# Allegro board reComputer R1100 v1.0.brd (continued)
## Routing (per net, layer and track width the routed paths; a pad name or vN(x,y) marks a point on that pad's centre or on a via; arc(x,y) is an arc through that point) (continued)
ISO_5V: length 16.1
  BOTTOM w1.016: R117.1 72.55,14.4 71.58,13.42 62.41,13.42 60.07,15.76 U22.4
LORA_3V3: length 7.8
  TOP w0.305: v1(71.25,36.59) 71.09,36.42 C112.2
  BOTTOM w0.305: J14.2 71.25,35.32 v1(71.25,36.59) ; J14.24 v1(59.24,34.03) ; J14.52 v1(44.25,35.32) 44.22,35.34 C114.2
  vias: v1(41.76,26.68) v1(41.76,26.2) v1(42.19,26.71) v1(42.19,26.22) v1(50.75,24.12) v1(50.75,23.66) v1(51.21,24.12) v1(51.21,23.66) v1(59.36,33.59)
LORAWAN_SX1262_CS: length 73.7
  TOP w0.121: v1(27.55,66.39) 28.18,67.02 U12.1
  LYR3 w0.121: v1(54.84,67.02) 55.36,67.02 55.9,66.48 55.9,52.82 56.61,52.11 56.61,37.69 57.03,37.27 57.46,37.27 58.73,36 58.73,33.9 57.69,32.85 57.69,29.27 v1(57.84,29.12)
  LYR6 w0.121: v1(27.55,66.39) 37.3,66.39 37.54,66.64 53.09,66.64 53.83,67.37 54.49,67.37 v1(54.84,67.02)
  BOTTOM w0.121: J14.25 58.84,28.22 58.64,28.42 58.1,28.42 57.84,28.69 v1(57.84,29.12)
LORAWAN_SX1262_RST: length 77.4
  TOP w0.121: U12.2 28.68,66.97 27.92,66.2 27.92,63.82 27.61,63.51 v1(27.61,62.9)
  LYR3 w0.121: v1(68.2,59.91) 69.78,58.33 69.78,47.99 70.89,46.87 70.89,39.35 v1(68.04,36.49)
  LYR6 w0.121: v1(68.2,59.91) 67.27,59.91 62.83,64.34 56.25,64.34 53.23,61.33 29.52,61.33 28.5,62.34 28.17,62.34 v1(27.61,62.9)
  BOTTOM w0.121: J14.10 v1(68.04,36.49)
LORAWAN_SX1302_RST: length 79.1
  TOP w0.121: v1(60.61,34) 60.61,33.67 59.99,33.05 R110.2 ; U12.3 29.18,66.92 28.22,65.97 v1(28.22,63.44)
  LYR3 w0.121: v1(65.48,63.41) 65.48,59.04 66.55,57.97 66.55,41.87 65.89,41.21 65.89,39.66 60.61,34.38 v1(60.61,34)
  LYR6 w0.121: v1(28.22,63.44) 28.78,63.44 29.84,62.38 31.49,62.38 31.85,62.01 52.86,62.01 56.09,65.24 63.65,65.24 v1(65.48,63.41)
LTE_LED_WWAN#: length 142.4
  TOP w0.121: J25.6 15.65,4.12 v1(14.68,5.09)
  LYR3 w0.121: v1(73.97,48.02) 78.08,43.9 78.08,33.36 78.33,33.12 82.41,33.12 84.15,34.85 v1(84.15,36.61) ; v1(24.79,55.49) 24.79,51.31 13.26,39.77 13.26,38.85 12.4,37.99 10.12,37.99 9.45,37.32 9.45,28.89 12.47,25.87 12.47,23.86 10.87,22.26 10.87,13.07 14.84,9.11 14.84,5.24 v1(14.68,5.09)
  LYR6 w0.121: v1(73.97,48.02) 73.74,47.79 52.48,47.79 47.25,53.02 35.71,53.02 35.26,53.48 32.72,53.48 32.26,53.02 29.26,53.02 26.8,55.49 v1(24.79,55.49)
  BOTTOM w0.121: J15.42 v1(84.15,36.61)
LTE_RESET: length 95.2
  TOP w0.121: v1(28.32,62.78) 28.68,63.13 28.68,65.96 29.68,66.96 U12.4
  LYR3 w0.121: v1(94.39,39.91) 94.57,40.09 94.57,42.07 89.82,46.82 v1(89.82,60.59)
  LYR6 w0.121: v1(28.32,62.78) 28.63,62.78 29.47,61.94 31.27,61.94 31.54,61.66 53.09,61.66 56.11,64.68 62.97,64.68 67.21,60.44 69.98,60.44 70.56,59.85 74.2,59.85 74.93,60.59 89.81,60.59 v1(89.82,60.59)
  BOTTOM w0.121: R109.2 v1(94.39,39.91)
NEXTRST: length 44.2
  TOP w0.121: v1(60.86,36.66) 59.79,35.6 58.47,35.6 58.24,35.37 R46.1 ; J4.100 v1(54.2,72.08)
  LYR3 w0.121: v1(54.2,72.08) 54.2,70.73 57.38,67.55 59.13,67.55 61.78,64.91 61.78,44.16 60.86,43.24 v1(60.86,36.66)
NLNKA_LED: length 24.8
  TOP w0.121: R83.1 v1(44.1,23.51) ; U4.21 52.34,37.41 50.9,38.85 46.08,38.85 45.37,38.14 45.37,36.87 v1(45.65,36.59)
  LYR3 w0.121: v1(45.65,36.59) 45.65,36.31 46.08,35.88 46.08,27.34 44.1,25.36 v1(44.1,23.51)
NPIBOOT: length 94.9
  TOP w0.121: v1(38.81,71.11) 40.05,69.87 45.51,69.87 50.01,74.38 54.99,74.38 55.4,74.79 J4.93
  LYR3 w0.121: J6.2 3.02,33.97 6.07,33.97 6.71,34.61 6.71,41.49 8.11,42.89 13.52,42.89 21.49,50.86 21.49,74.76 v1(22.58,75.86)
  LYR6 w0.121: v1(38.81,71.11) 34.52,75.4 23.04,75.4 v1(22.58,75.86)
NPWR_LED: length 122
  TOP w0.121: v1(12.42,5.57) 11.41,5.57 10.65,4.82 J25.1 ; J4.95 55,74.83 54.83,74.65 49.94,74.65 45.4,70.12 40.59,70.12 v1(39.45,71.26)
  LYR3 w0.121: v1(12.42,5.57) 12.42,10.47 7.99,14.9 7.99,21.4 6.36,23.03 6.36,26.5 7.71,27.85 7.71,37.66 9.04,38.99 11.93,38.99 12.25,39.31 12.25,40.19 23.27,51.22 23.27,59.3 23.75,59.78 23.75,63.36 23.24,63.87 23.24,68.92 22.91,69.25 22.91,75.25 v1(23.5,75.83)
  LYR6 w0.121: v1(23.5,75.83) 34.72,75.83 39.3,71.26 v1(39.45,71.26)
NSPD_LED: length 22.8
  TOP w0.121: v1(46.23,36.49) 46.23,38.19 46.61,38.57 50.78,38.57 51.84,37.51 U4.22 ; R84.1 v1(45.14,23.5)
  LYR3 w0.121: v1(46.23,36.49) 46.33,36.39 46.33,27.23 45.08,25.99 45.08,23.56 v1(45.14,23.5)
PCIE_CLK_N: length 88.7
  TOP w0.095: J5.112 71.8,39.03 71.86,39.09 71.86,39.44 72.12,39.7 75.34,39.7 76.58,40.95 76.58,56.3 77.02,56.73 77.64,56.73 77.75,56.84 v1(77.97,56.84)
  LYR6 w0.102: v1(18.93,56.94) 19.03,56.84 29.32,56.84 31.07,58.58 53.22,58.58 55.06,56.74 77.65,56.74 77.75,56.84 v1(77.97,56.84)
  BOTTOM w0.095: v1(18.93,56.94) 18.81,56.83 14.71,56.83 14.6,56.94 J62.53
PCIE_CLK_NREQ: length 90.1
  TOP w0.121: J5.102 75.83,38.75 77.83,40.75 77.83,54.6 78.97,55.74 78.97,62.7 v1(77.19,64.48)
  BOTTOM w0.121: v1(77.19,64.48) 76.17,65.5 56.92,65.5 54.43,63.01 41.38,63.01 36.68,58.31 32.57,58.31 32.04,57.78 22.62,57.78 22.02,57.19 J62.52
PCIE_CLK_P: length 88.6
  TOP w0.095: J5.110 72.2,39.03 72.14,39.09 72.14,39.33 72.24,39.42 73.97,39.42 74.09,39.29 74.45,39.29 74.58,39.42 75.45,39.42 76.86,40.83 76.86,41.19 76.99,41.31 76.99,41.67 76.86,41.79 76.86,54 76.99,54.13 76.99,54.48 76.86,54.61 76.86,54.96 76.99,55.09 76.99,55.45 76.86,55.57 76.86,56.18 77.13,56.45 77.64,56.45 77.75,56.34 v1(77.97,56.34)
  LYR6 w0.102: v1(18.93,56.43) 19.03,56.54 29.45,56.54 31.19,58.28 53.09,58.28 54.93,56.44 77.65,56.44 77.75,56.34 v1(77.97,56.34)
  BOTTOM w0.095: J62.55 14.6,56.44 14.71,56.55 18.81,56.55 v1(18.93,56.43)
PCIE_NRST: length 77
  TOP w0.121: J5.109 72.2,58.32 69.8,60.72 69.8,65.11 69.01,65.9 v1(67.59,65.9)
  BOTTOM w0.121: v1(67.59,65.9) 56.9,65.9 54.26,63.26 41.28,63.26 36.58,58.56 32.46,58.56 31.93,58.03 22.26,58.03 21.91,57.69 J62.50
PCIE_RX_N: length 91.4
  TOP w0.095: J5.118 70.6,39.03 70.66,39.09 70.66,39.64 71.44,40.41 74.42,40.41 75.54,41.53 75.54,58.87 75.86,59.19 76.23,59.19 76.34,59.31 v1(76.56,59.31)
  LYR6 w0.102: v1(18.9,59.94) 19,59.84 28.97,59.84 29.64,60.51 54.05,60.51 57.36,63.82 62.38,63.82 67,59.21 76.24,59.21 76.34,59.31 v1(76.56,59.31)
  BOTTOM w0.095: v1(18.9,59.94) 18.79,59.83 14.71,59.83 14.6,59.94 J62.41
PCIE_RX_P: length 91.4
  TOP w0.095: v1(76.56,58.8) 76.34,58.8 76.23,58.91 75.98,58.91 75.82,58.76 75.82,58.4 75.95,58.28 75.95,57.92 75.82,57.79 75.82,57.44 75.95,57.31 75.95,56.96 75.82,56.83 75.82,44.23 75.95,44.11 75.95,43.75 75.82,43.62 75.82,41.41 75.22,40.82 75.22,40.64 74.97,40.38 74.79,40.38 74.54,40.13 71.55,40.13 70.94,39.52 70.94,39.09 71,39.03 J5.116
  LYR6 w0.102: v1(76.56,58.8) 76.34,58.8 76.24,58.9 66.87,58.9 62.26,63.51 57.48,63.51 54.18,60.21 29.77,60.21 29.1,59.54 19,59.54 v1(18.9,59.43)
  BOTTOM w0.095: J62.43 14.6,59.44 14.71,59.55 18.79,59.55 v1(18.9,59.43)
PCIE_TX_N: length 87.4
  TOP w0.095: v1(74.56,58.43) 74.68,58.32 74.68,44.46 74.55,44.33 74.55,43.98 74.68,43.85 74.68,43.5 74.55,43.37 74.55,43.01 74.68,42.89 74.68,41.89 73.94,41.15 70.4,41.15 69.46,40.21 69.46,39.09 69.4,39.03 J5.124
  LYR6 w0.102: v1(18.9,58.44) 19,58.34 29.04,58.34 30.36,59.65 53.95,59.65 55.86,57.75 70.56,57.75 70.69,57.87 71.05,57.87 71.17,57.75 71.53,57.75 71.66,57.87 72.01,57.87 72.14,57.75 72.49,57.75 72.62,57.87 72.98,57.87 73.1,57.75 73.46,57.75 73.59,57.87 73.94,57.87 74.07,57.75 74.54,57.75 74.67,57.87 74.67,58.33 v1(74.56,58.43)
  BOTTOM w0.095: J62.47 14.6,58.44 14.72,58.33 18.79,58.33 v1(18.9,58.44)
PCIE_TX_P: length 87.4
  TOP w0.095: v1(75.07,58.43) 74.96,58.32 74.96,41.77 74.06,40.87 70.51,40.87 70.3,40.65 70.3,40.49 70.06,40.25 69.89,40.25 69.74,40.1 69.74,39.09 69.8,39.03 J5.122
  LYR6 w0.102: v1(18.9,57.93) 19,58.03 29.17,58.03 30.48,59.35 53.83,59.35 55.73,57.44 74.67,57.44 74.97,57.74 74.97,58.33 v1(75.07,58.43)
  BOTTOM w0.095: v1(18.9,57.93) 18.79,58.05 14.72,58.05 14.6,57.94 J62.49
PCIE_USIM_PRESE: length 34.2
  LYR3 w0.121: v1(84.43,57.82) 85.24,57.01 v1(85.24,37.12)
  BOTTOM w0.121: J15.44 83.35,36.9 83.57,37.12 v1(85.24,37.12) ; R114.2 77.55,54.67 J16.SW 79.86,55.21 82.48,57.82 v1(84.43,57.82)
PL_NLED: length 126.8
  TOP w0.121: v1(69.98,74.94) 69.8,75.12 J4.21 ; v1(11.56,4.76) 11.65,4.67 J25.2
  LYR3 w0.121: v1(11.56,4.76) 11.56,10.63 7.5,14.7 7.5,21.2 5.86,22.83 5.86,26.71 7.21,28.05 7.21,41.28 8.31,42.39 13.72,42.39 22.71,51.37 22.71,60.06 22.84,60.18 22.84,64.45 v1(22.71,64.58)
  BOTTOM w0.121: v1(22.71,64.58) 22.72,64.57 38.3,64.57 39.39,65.66 44.83,65.66 48.34,69.18 61.07,69.18 61.96,70.07 66.86,70.07 67.06,70.27 67.06,71.94 69.98,74.87 v1(69.98,74.94)
POE_12V:
  vias: v1(35.49,44.21) v1(35.49,43.78) v1(35.47,43.33) v1(35.47,42.85) v1(35.94,44.18) v1(35.94,43.75) v1(35.93,43.31) v1(35.93,42.82)
POE_IN_N:
  vias: v1(13.97,8.47) v1(14.18,9) v1(14.46,8.47) v1(19.97,17.66) v1(20.4,17.66) v1(20.83,17.66) v1(25.35,19.67) v1(25.35,19.21) v1(25.78,19.65) v1(25.78,19.19) v1(33.56,16.39) v1(33.56,15.89) v1(33.56,15.43) v1(33.56,14.97)
RS485_POWER_EN: length 96.6
  TOP w0.121: U12.14 v1(30.18,73.27)
  LYR3 w0.121: v1(80.85,24.22) 79.1,24.22 77.75,25.56 77.75,43.6 72.21,49.14 72.21,65.82 v1(70.89,67.14) ; v1(30.76,66.89) 30.76,67.83 29.92,68.67 29.92,73.14 30.04,73.27 v1(30.18,73.27)
  LYR6 w0.121: v1(70.89,67.14) 56.42,67.14 55.83,67.73 53.19,67.73 52.5,67.04 37.47,67.04 37.09,66.66 31.93,66.66 31.7,66.89 v1(30.76,66.89)
RTC_INT: length 6.5
  TOP w0.121: U16.3 v1(11.53,69.76)
  BOTTOM w0.121: C109.1 12.21,73.76 R104.2 10.72,73.22 10.72,70.57 v1(11.53,69.76)
RUN_PG: length 98.2
  TOP w0.121: J4.92 55.8,72.17 55.3,71.67 49.15,71.67 v1(48.9,71.92)
  LYR3 w0.121: v1(48.9,71.92) 48.9,71.72 43.61,66.43 43.61,53.28 34.67,44.33 34.67,31.41 39.21,26.87 39.21,24.99 39.7,24.5 39.7,22.59 38.36,21.25 v1(37.82,21.25)
  LYR6 w0.121: v1(37.82,21.25) 35.84,21.25 34.75,20.15 31.42,20.15 29.75,18.48 18.77,18.48 17.1,16.81 10.97,16.81 v1(9.83,17.94)
  BOTTOM w0.121: R36.2 9.83,17.94 v1(9.83,17.94)
SD_DET: length 19.5
  TOP w0.121: R87.1 18.52,65.9 19.05,65.37 20.53,65.37 21.67,66.51 21.67,72.22 23.83,74.38 27.66,74.38 v1(28.7,73.34) 29.18,72.87 U12.16
SD_VDD_OVERRIDE: length 2.8
  TOP w0.121: J4.73 59.4,78.02 R26.1
TPM_RST: length 70.6
  TOP w0.121: U12.5 30.18,65.62 30.69,65.11 30.69,62.52 30.43,62.27 26.41,62.27 v1(26.08,61.94)
  LYR3 w0.121: v1(17.1,17.56) 17.1,17.59 15.01,19.67 13.06,19.67 12.58,20.15 12.58,23.26 12.97,23.66 12.97,26.07 10,29.04 10,37.09 10.41,37.5 12.67,37.5 23.98,48.81 25.3,48.81 25.96,49.47 25.96,56.05 26.7,56.79 26.7,58.08 26.08,58.69 v1(26.08,61.94)
  BOTTOM w0.121: J13.3 v1(17.1,17.56)
TRCT: length 32.5
  TOP w0.305: v1(47.52,22.1) C88.1 47.09,22.11 R82.2
  BOTTOM w0.305: 50.45,5.79 J10.12 ; 50.45,5.79 50.08,5.79 ; 50.45,5.79 50.27,5.98 ; 50.08,5.79 48.56,4.27 J10.9 ; 50.08,5.79 50.27,5.98 ; 50.27,5.98 J10.5 49,16.79 J10.4 49,20.21 47.52,21.68 v1(47.52,22.1)
UART_3V3: length 103.2
  TOP w0.254: U15.1 35.09,55.19 34.8,55.49 34.8,56.48 v1(34.72,56.55) 34.8,56.63 C100.2 ; R91.1 35.97,50.58 35.59,50.2 30.53,50.2 30.2,50.53 30.2,52.46 30.76,53.02 v1(33.38,53.02) 33.64,53.28 R98.1
  LYR3 w0.381: v1(54.82,21.35) 54.82,20.28 57.61,17.49 57.61,15.25 59.34,13.52 59.34,7.5 v1(59.79,7.05) ; v1(32.9,23.79) 32.9,25.92 v1(29.12,29.69) 28.32,30.49 28.32,36.21 25.89,38.65 25.89,46.93 30.28,51.32 33.33,51.32 33.82,51.82 33.82,52.58 v1(33.38,53.02) 33.38,53.33 33.78,53.73 33.78,55.61 v1(34.72,56.55)
  LYR6 w0.381: v1(54.82,21.35) 54.76,21.4 50.06,21.4 48.57,22.9 38.51,22.9 37.67,23.74 32.94,23.74 v1(32.9,23.79)
  BOTTOM w0.381: v1(29.12,29.69) 29.14,29.68 D24.1 ; v1(59.79,7.05) 59.92,6.92 TP21.1
USB1_RST: length 65.6
  TOP w0.121: U4.12 56.24,33.98 C55.1 56.74,34.75 56.92,34.94 57.6,34.94 58.22,34.32 R46.2 ; R46.2 R44.2 ; R46.2 58.51,34.32 58.78,34.58 58.78,35.01 59.01,35.24 60.28,35.24 61.29,36.26 v1(61.29,37.17) ; v1(77.27,72.76) 77.27,69.15 v1(76.63,68.52)
  LYR3 w0.121: v1(58.8,68.16) 59.06,68.16 62.05,65.16 62.05,43.9 61.19,43.04 61.19,37.27 v1(61.29,37.17)
  BOTTOM w0.121: R64.1 v1(77.27,72.76) ; v1(76.63,68.52) 62.41,68.52 62.05,68.16 v1(58.8,68.16)
USB2_RST: length 17.4
  TOP w0.121: U5.26 v1(94.87,67.95)
  BOTTOM w0.121: U6.2 81.07,73.61 R71.2 81.89,73.61 82.4,73.1 R59.2 R52.2 C61.1 88.16,68.8 93.65,68.8 94.5,67.95 v1(94.87,67.95)
USB2_RST_EN: length 57.1
  TOP w0.121: v1(33.05,71.26) 33.05,71.72 32.21,72.56 U12.13
  LYR6 w0.121: v1(33.05,71.26) 33.35,70.95 35.03,70.95 37.44,68.54 47.25,68.54 52.83,74.13 61.24,74.13 61.72,74.61 67.26,74.61 67.59,74.28 69.95,74.28 70.34,74.66 71.58,74.66 72.54,73.7 77.29,73.7 78.28,72.71 v1(81.86,72.71)
  BOTTOM w0.121: R71.1 v1(81.86,72.71)
USB2_VBUS_EN1: length 8.2
  TOP w0.121: R65.1 99.6,73.32 v1(99.49,73.21) 99.49,73.16 99.4,73.07 U5.12 ; v1(101.46,72.41) 101.6,72.27 102.57,72.27 102.81,72.52 R75.2 103.29,73.38 103.67,73.76 U7.1
  LYR6 w0.121: v1(101.46,72.41) 100.54,73.34 99.62,73.34 v1(99.49,73.21)
USB2_VBUS_EN2: length 11.5
  TOP w0.121: R74.2 103.65,69.95 v1(103.66,69.96) 103.68,69.95 U7.4 ; U5.16 97.4,73 v1(97.23,73.16) 97.26,73.19 R66.1
  LYR6 w0.121: v1(97.23,73.16) 97.28,73.16 97.89,72.55 100.69,72.55 101.22,72.02 103.33,72.02 103.66,71.69 v1(103.66,69.96)
USB2_VRCURN1: length 9.8
  TOP w0.121: v1(105.72,72.53) 105.68,72.49 U7.2 ; U5.13 v1(98.9,73.2) 98.92,73.22 R60.1
  LYR6 w0.121: v1(98.9,73.2) 98.9,73.26 99.34,73.7 104.55,73.7 v1(105.72,72.53)
USB2_VRCURN2: length 14.8
  TOP w0.121: v1(105.74,71.21) 105.69,71.21 105.68,71.22 U7.3 ; R61.1 96.59,73.22 v1(96.6,73.21) 96.9,72.91 U5.17
  LYR6 w0.121: v1(96.6,73.21) 97.39,74 105.31,74 106.2,73.11 106.2,71.67 v1(105.74,71.21)
USB_0M: length 15.5
  TOP w0.114: U3.7 v1(58.72,29.59) ; U4.58 51.34,28.32 51.45,28.43 51.45,28.69 v1(51.34,28.8)
  LYR3 w0.127: v1(51.34,28.8) 51.34,29.05 51.44,29.15 51.44,29.53 51.74,29.83 52.94,29.83 53.75,29.02 53.75,28.36 54.31,27.8 59.16,27.8 59.44,28.08 59.44,28.21 59.75,28.51 59.87,28.51 60.12,28.76 60.12,29.46 60,29.59 v1(58.72,29.59)
USB_0P: length 15.5
  TOP w0.114: v1(51.84,28.8) 51.73,28.69 51.73,28.43 51.84,28.32 U4.59 ; U3.1 v1(61.84,29.59)
  LYR3 w0.127: v1(61.84,29.59) 60.56,29.59 60.43,29.46 60.43,28.64 59.29,27.49 54.18,27.49 53.44,28.23 53.44,28.89 52.81,29.53 51.87,29.53 51.74,29.4 51.74,29.15 51.84,29.05 v1(51.84,28.8)
USB_1M: length 42.8
  TOP w0.114: U3.6 v1(59.09,29.99)
  LYR3 w0.127: v1(35.97,24.25) 37.19,24.25 37.32,24.12 37.32,23.94 36.55,23.18 36.55,21.2 38.74,19.01 41.91,19.01 45.52,22.62 53.57,22.62 54.66,23.71 57.38,23.71 62.63,28.96 62.63,30.22 61.98,30.87 60.56,30.87 60.11,30.42 60.11,30.12 59.98,29.99 v1(59.09,29.99)
  BOTTOM w0.114: U14.6 v1(35.97,24.25)
USB_1P: length 42.8
  TOP w0.114: U3.2 v1(61.44,29.99)
  LYR3 w0.127: v1(38.97,24.25) 37.75,24.25 37.62,24.12 37.62,23.82 36.85,23.05 36.85,22.69 36.98,22.57 36.98,22.21 36.85,22.08 36.85,21.33 37.99,20.19 38.17,20.19 38.42,19.94 38.42,19.76 38.86,19.32 39.22,19.32 39.35,19.44 39.7,19.44 39.83,19.32 40.44,19.32 40.57,19.44 40.92,19.44 41.05,19.32 41.79,19.32 42.24,19.77 42.24,19.95 42.49,20.2 42.67,20.2 43.16,20.69 43.16,20.87 43.41,21.12 43.59,21.12 44.16,21.69 44.16,21.87 44.41,22.12 44.59,22.12 45.39,22.92 45.85,22.92 45.98,23.05 46.33,23.05 46.46,22.92 47.37,22.92 47.5,23.05 47.86,23.05 47.98,22.92 48.8,22.92 48.92,23.05 49.28,23.05 49.41,22.92 49.89,22.92 50.02,23.05 50.37,23.05 50.5,22.92 51.51,22.92 51.64,23.05 52,23.05 52.12,22.92 52.48,22.92 52.61,23.05 52.96,23.05 53.09,22.92 53.44,22.92 54.54,24.01 54.89,24.01 55.02,24.14 55.37,24.14 55.5,24.01 55.86,24.01 55.98,24.14 56.34,24.14 56.47,24.01 57.25,24.01 59.49,26.25 59.49,26.43 59.74,26.68 59.92,26.68 60.17,26.93 60.17,27.11 60.42,27.36 60.6,27.36 60.85,27.61 60.85,27.79 61.1,28.04 61.28,28.04 61.53,28.3 61.53,28.47 61.79,28.73 61.97,28.73 62.32,29.08 62.32,30.1 61.85,30.57 60.69,30.57 60.42,30.3 60.42,30.12 60.54,29.99 v1(61.44,29.99)
  BOTTOM w0.114: U14.2 v1(38.97,24.25)
USB_C_DM: length 40
  TOP w0.114: R530.2 59.24,10.18 59.24,10.35 59.62,10.73 59.62,13.45 57.08,15.99 55.11,15.99 v1(54.99,16.1)
  LYR3 w0.127: v1(36.77,19.47) 36.77,19.22 36.87,19.12 36.87,18.28 37.38,17.77 42.29,17.77 45.8,21.27 51.46,21.27 51.59,21.14 51.95,21.14 52.07,21.27 52.43,21.27 53.11,20.59 53.11,20.41 53.37,20.15 53.55,20.15 53.83,19.87 53.83,19.7 54.08,19.44 54.26,19.44 55.68,18.02 55.68,17.51 55.55,17.39 55.55,17.03 55.68,16.9 55.68,16.24 55.44,16 55.1,16 v1(54.99,16.1)
  BOTTOM w0.114: U14.5 37.06,22.77 37.32,22.52 37.32,22.15 36.88,21.72 36.88,19.8 36.77,19.69 v1(36.77,19.47)
USB_C_DP: length 40
  TOP w0.114: v1(54.99,15.59) 55.11,15.71 55.46,15.71 55.59,15.58 55.95,15.58 56.07,15.71 56.96,15.71 57.21,15.46 57.21,15.28 57.46,15.03 57.64,15.03 59.34,13.33 59.34,12.98 59.21,12.85 59.21,12.49 59.34,12.37 59.34,11.81 59.21,11.68 59.21,11.33 59.34,11.2 59.34,10.85 58.96,10.47 58.96,10.19 R531.2
  LYR3 w0.127: v1(54.99,15.59) 55.1,15.7 55.56,15.7 55.98,16.12 55.98,18.15 52.56,21.58 45.67,21.58 42.17,18.07 37.51,18.07 37.18,18.4 37.18,19.12 37.28,19.22 v1(37.28,19.47)
  BOTTOM w0.114: v1(37.28,19.47) 37.28,19.69 37.16,19.8 37.16,21.6 37.59,22.03 37.59,22.52 37.86,22.79 U14.3
USB_DET: length 22.6
  TOP w0.121: U5.27 v1(94.64,67.45)
  BOTTOM w0.121: v1(94.64,67.45) 94.44,67.45 93.55,68.34 88.01,68.34 84.51,71.84 76.96,71.84 76.57,72.24 R51.2 C60.1
USB_DM: length 24.7
  TOP w0.114: v1(60.01,32.46) 60.12,32.35 60.12,31.56 59.88,31.31 U3.5 ; J5.103 73.4,42.42 73.34,42.48 73.34,43.03 73.46,43.15 v1(73.46,43.37)
  LYR3 w0.127: v1(73.46,43.37) 73.46,43.12 73.35,43.02 73.35,40.7 69.5,36.84 69.5,35.72 66.17,32.4 62.13,32.4 61.34,31.61 60.42,31.61 60.11,31.91 60.11,32.36 v1(60.01,32.46)
USB_DP: length 24.6
  TOP w0.114: v1(72.95,43.37) 72.95,43.15 73.06,43.03 73.06,42.48 73,42.42 J5.105 ; U3.3 60.68,31.29 60.4,31.56 60.4,32.35 v1(60.52,32.46)
  LYR3 w0.127: v1(60.52,32.46) 60.42,32.36 60.42,32.04 60.54,31.91 61.22,31.91 62,32.7 62.36,32.7 62.49,32.83 62.84,32.83 62.97,32.7 63.58,32.7 63.71,32.83 64.06,32.83 64.19,32.7 64.54,32.7 64.67,32.83 65.03,32.83 65.15,32.7 66.04,32.7 66.29,32.95 66.29,33.13 66.55,33.38 66.73,33.38 68.51,35.17 68.51,35.35 68.76,35.6 68.94,35.6 69.19,35.85 69.19,36.97 70.16,37.93 70.16,38.11 70.41,38.37 70.59,38.37 70.92,38.7 70.92,38.88 71.18,39.13 71.36,39.13 71.61,39.38 71.61,39.56 71.86,39.82 72.04,39.82 72.29,40.07 72.29,40.25 72.54,40.5 72.72,40.5 73.05,40.83 73.05,43.02 72.95,43.12 v1(72.95,43.37)
USB_HUB1_DM2: length 23.2
  TOP w0.114: U4.1 55.67,28.48 v1(55.68,28.47) ; J22.3 65.41,18.93 65.3,19.05 64.34,19.05 63.55,19.84 63.55,24.11 v1(63.44,24.23)
  BOTTOM w0.114: v1(55.68,28.47) 55.79,28.58 56.16,28.58 58.5,30.92 59.51,30.92 60.02,30.42 61.93,30.42 63.55,28.79 63.55,27.4 63.35,27.2 63.35,26.94 63.55,26.74 63.55,26.48 63.35,26.28 63.35,26.03 63.55,25.82 63.55,25.57 63.35,25.37 63.35,25.11 63.55,24.91 63.55,24.34 v1(63.44,24.23)
USB_HUB1_DM3: length 80.3
  TOP w0.114: U5.30 97.4,65.96 97.51,65.85 97.51,64.67 97.04,64.2 95.8,64.2 95.54,63.94 95.38,63.94 95.27,64.05 95.11,64.05 94.95,63.89 94.95,63.73 95.06,63.62 95.06,63.46 94.91,63.31 94.14,63.31 v1(94.02,63.42) ; v1(58.99,31.65) 58.88,31.53 58.88,30.55 57.91,29.59 55.69,29.59 55.58,29.48 U4.3
  LYR3 w0.127: v1(58.99,31.65) 58.89,31.75 58.89,32 59.82,32.93 61.06,32.93 62.13,34 64.87,34 69.8,38.92 69.8,47.23 69.14,47.89 69.14,57.85 67.39,59.6 67.39,63.01 67.49,63.11 v1(67.49,63.36)
  LYR6 w0.127: v1(67.49,63.36) 67.49,63.11 67.39,63.01 67.39,62.7 68.13,61.96 68.48,61.96 68.61,62.09 68.96,62.09 69.09,61.96 70.16,61.96 70.28,62.09 70.64,62.09 70.77,61.96 71.71,61.96 72.6,62.85 72.95,62.85 73.08,62.98 73.43,62.98 73.56,62.85 74.12,62.85 74.25,62.98 74.6,62.98 74.73,62.85 88.55,62.85 89.02,63.32 93.68,63.32 93.78,63.42 v1(94.02,63.42)
USB_HUB1_DP2: length 23.2
  TOP w0.114: v1(55.68,28.98) U4.2 ; J22.5 65.41,19.44 65.3,19.33 64.46,19.33 63.83,19.95 63.83,21.28 63.95,21.39 64.1,21.39 64.21,21.51 64.21,21.73 64.1,21.85 63.95,21.85 63.83,21.96 63.83,24.11 v1(63.95,24.23)
  BOTTOM w0.114: v1(63.95,24.23) 63.83,24.34 63.83,28.91 62.04,30.7 60.14,30.7 59.63,31.2 58.39,31.2 56.05,28.86 55.79,28.86 v1(55.68,28.98)
USB_HUB1_DP3: length 80.3
  TOP w0.114: v1(94.02,62.92) 94.14,63.03 95.02,63.03 95.91,63.92 97.16,63.92 97.79,64.55 97.79,65.85 97.9,65.96 U5.31 ; U4.4 55.58,29.98 55.69,29.87 57.8,29.87 57.93,30 57.93,30.16 57.85,30.24 57.85,30.4 58.01,30.57 58.18,30.57 58.26,30.49 58.42,30.49 58.6,30.67 58.6,31.53 v1(58.49,31.65)
  LYR3 w0.127: v1(66.98,63.36) 66.98,63.11 67.08,63.01 67.08,59.47 68.84,57.72 68.84,47.76 69.5,47.1 69.5,39.05 64.75,34.3 62,34.3 60.94,33.24 59.69,33.24 58.59,32.13 58.59,31.75 v1(58.49,31.65)
  LYR6 w0.127: v1(66.98,63.36) 66.98,63.11 67.08,63.01 67.08,62.57 68,61.66 71.83,61.66 72.72,62.55 88.67,62.55 89.14,63.02 93.68,63.02 93.78,62.92 v1(94.02,62.92)
USB_HUB2_DM1: length 24.2
  TOP w0.114: U5.1 101.89,67.45 102,67.56 102.35,67.56 102.46,67.45 v1(102.68,67.45)
  LYR6 w0.127: v1(102.68,67.45) 102.58,67.55 102.31,67.55 102.19,67.42 102.19,66.79 103.99,64.99 103.99,64.22 104.68,63.54 115.85,63.54 117.05,62.34 117.05,60.79 115.98,59.73 115.23,59.73 v1(115.13,59.63)
  BOTTOM w0.114: v1(115.13,59.63) 115.11,59.63 115.1,59.62 L4.4
USB_HUB2_DM2: length 24.3
  TOP w0.114: U5.3 v1(101.93,68.45)
  LYR6 w0.127: v1(101.93,68.45) 101.69,68.45 101.59,68.55 101.35,68.55 101.22,68.42 101.22,68.07 101.35,67.94 101.35,67.59 101.22,67.46 101.22,66.1 101.35,65.98 101.35,65.62 101.22,65.49 101.22,65.01 101.47,64.76 101.65,64.76 101.9,64.51 101.9,64.33 102.16,64.08 102.34,64.08 102.59,63.83 102.59,63.65 102.84,63.4 103.02,63.4 103.27,63.14 103.27,62.97 103.52,62.71 103.7,62.71 103.95,62.46 103.95,62.28 104.2,62.03 104.38,62.03 104.64,61.78 104.64,61.6 105.14,61.1 106,61.1 106.12,61.23 106.48,61.23 106.61,61.1 106.96,61.1 107.09,61.23 107.44,61.23 107.57,61.1 107.93,61.1 108.05,61.23 108.41,61.23 108.54,61.1 108.89,61.1 109.02,61.23 109.37,61.23 109.5,61.1 109.86,61.1 109.98,61.23 110.34,61.23 110.47,61.1 110.82,61.1 110.95,61.23 111.31,61.23 111.43,61.1 111.79,61.1 111.91,61.23 112.27,61.23 112.4,61.1 112.75,61.1 112.88,61.23 113.24,61.23 113.36,61.1 114.24,61.1 114.36,61.23 114.36,61.28 114.49,61.4 114.75,61.4 114.87,61.28 114.87,61.23 115,61.1 115.34,61.1 115.65,61.4 115.65,61.84 115.52,61.96 115.27,61.96 v1(115.17,61.86)
  BOTTOM w0.114: L5.2 115.13,61.85 115.14,61.86 v1(115.17,61.86)
USB_HUB2_DM3: length 113.6
  TOP w0.114: U5.6 101.89,69.95 102,70.06 102.37,70.06 102.49,69.95 v1(102.71,69.95)
  LYR3 w0.127: v1(46.23,65.21) 46.33,65.11 46.33,50.43 38.47,42.57 38.47,37.41 v1(38.37,37.31)
  LYR6 w0.127: v1(46.23,65.21) 46.33,65.11 46.33,64.73 46.64,64.43 54.59,64.43 55.98,65.82 64.95,65.82 65.61,65.16 83.75,65.16 84.84,64.07 86.95,64.07 88.04,65.16 95.89,65.16 100.77,70.05 102.36,70.05 102.46,69.95 v1(102.71,69.95)
  BOTTOM w0.114: v1(38.37,37.31) 38.48,37.2 38.48,36.55 38.88,36.16 40.86,36.16 42.89,34.12 45.71,34.12 46.67,33.16 53.81,33.16 54.18,33.53 54.18,33.87 54.44,34.13 J14.36
USB_HUB2_DM4: length 50.2
  TOP w0.114: U5.8 v1(101.93,70.95)
  LYR3 w0.127: v1(86.29,65.29) 86.29,65.05 86.18,64.94 86.18,37.04 86.39,36.83 v1(86.39,36.59)
  LYR6 w0.127: v1(86.29,65.29) 86.29,65.53 86.18,65.64 86.18,66.53 86.41,66.76 87.23,66.76 87.35,66.64 87.71,66.64 87.84,66.76 88.37,66.76 88.5,66.64 88.85,66.64 88.98,66.76 89.33,66.76 89.46,66.64 89.82,66.64 89.94,66.76 90.45,66.76 90.58,66.64 90.93,66.64 91.06,66.76 95.66,66.76 99.95,71.05 101.59,71.05 101.69,70.95 v1(101.93,70.95)
  BOTTOM w0.114: J15.36 86.55,36.47 86.43,36.59 v1(86.39,36.59)
USB_HUB2_DP1: length 24.2
  TOP w0.114: U5.2 101.89,67.95 102,67.84 102.35,67.84 102.46,67.95 v1(102.68,67.95)
  LYR6 w0.127: v1(102.68,67.95) 102.58,67.85 102.19,67.85 101.88,67.55 101.88,66.66 103.69,64.86 103.69,64.1 104.55,63.23 115.73,63.23 116.74,62.22 116.74,60.92 115.86,60.04 115.23,60.04 v1(115.13,60.14)
  BOTTOM w0.114: v1(115.13,60.14) 115.11,60.12 L4.1
USB_HUB2_DP2: length 24.5
  TOP w0.114: U5.4 101.92,68.95 v1(101.93,68.96)
  LYR6 w0.127: v1(115.17,62.37) 115.27,62.27 115.65,62.27 115.95,61.96 115.95,61.28 115.47,60.79 105.01,60.79 100.92,64.89 100.92,68.55 101.22,68.86 101.59,68.86 101.69,68.96 v1(101.93,68.96)
  BOTTOM w0.114: L5.3 115.15,62.35 v1(115.17,62.37)
USB_HUB2_DP3: length 113.5
  TOP w0.114: v1(102.71,70.45) 102.49,70.45 102.37,70.34 102,70.34 101.89,70.45 U5.7
  LYR3 w0.127: v1(38.88,37.31) 38.78,37.41 38.78,42.44 46.64,50.3 46.64,65.11 v1(46.74,65.21)
  LYR6 w0.127: v1(102.71,70.45) 102.46,70.45 102.36,70.35 100.64,70.35 95.76,65.47 87.91,65.47 86.82,64.38 84.97,64.38 83.87,65.47 65.74,65.47 65.08,66.13 55.86,66.13 54.46,64.73 51.72,64.73 51.59,64.86 51.23,64.86 51.11,64.73 50.75,64.73 50.62,64.86 50.27,64.86 50.14,64.73 49.56,64.73 49.43,64.86 49.08,64.86 48.95,64.73 48.29,64.73 48.16,64.86 47.81,64.86 47.68,64.73 46.76,64.73 46.64,64.86 46.64,65.11 v1(46.74,65.21)
  BOTTOM w0.114: v1(38.88,37.31) 38.76,37.2 38.76,36.66 38.99,36.44 39.35,36.44 39.47,36.56 39.83,36.56 39.96,36.44 40.97,36.44 41.22,36.18 41.4,36.18 41.66,35.93 41.66,35.75 41.91,35.5 42.09,35.5 42.34,35.25 42.34,35.07 43,34.4 45.82,34.4 46.11,34.12 46.29,34.12 46.54,33.87 46.54,33.69 46.79,33.44 47.53,33.44 47.65,33.57 48.01,33.57 48.14,33.44 48.77,33.44 48.9,33.57 49.25,33.57 49.38,33.44 49.96,33.44 50.09,33.57 50.45,33.57 50.57,33.44 51.06,33.44 51.18,33.57 51.54,33.57 51.67,33.44 52.17,33.44 52.3,33.57 52.66,33.57 52.78,33.44 53.7,33.44 53.9,33.64 53.9,33.87 53.64,34.13 J14.38
USB_HUB2_DP4: length 50.2
  TOP w0.114: v1(101.93,71.46) 101.92,71.45 U5.9
  LYR3 w0.127: v1(85.78,65.29) 85.78,65.05 85.88,64.94 v1(85.88,36.59)
  LYR6 w0.127: v1(101.93,71.46) 101.69,71.46 101.59,71.36 99.82,71.36 95.53,67.07 86.29,67.07 85.88,66.66 85.88,65.64 85.78,65.53 v1(85.78,65.29)
  BOTTOM w0.114: v1(85.88,36.59) 85.86,36.59 85.75,36.47 J15.38
USB_OTG_ID: length 86.6
  TOP w0.121: U3.10 61.98,28.97 v1(62.89,28.05) ; v1(74.25,42.13) 74.09,42.13 J5.101
  LYR3 w0.121: v1(74.25,42.13) 74.25,37.91 64.39,28.05 v1(62.89,28.05) 61.9,27.06 v1(61.9,24.55)
  LYR6 w0.121: v1(10.44,30.39) 10.44,29.3 11.99,27.75 31.27,27.75 33.74,25.28 v1(38.18,25.28) 39.84,25.28 41,24.12 47.88,24.12 49.99,22.01 56.72,22.01 59.26,24.55 v1(61.9,24.55)
  BOTTOM w0.121: v1(10.44,30.39) C37.1 9.98,30.64 R35.1 9.98,32.11 R34.2 ; U14.10 v1(38.18,25.28)
USB_OTG_ID1: length 4.3
  BOTTOM w0.121: R34.1 8.8,32.78 J6.5
USB_TO_UART_DM: length 35.5
  TOP w0.114: U15.8 37.64,52.78 37.53,52.67 37.53,51.48 37.77,51.24 37.93,51.24 38.01,51.32 38.18,51.32 38.34,51.16 38.34,51 38.26,50.92 38.26,50.76 38.71,50.3 39.19,50.3 v1(39.31,50.42)
  LYR3 w0.127: v1(39.31,50.42) 39.21,50.32 38.8,50.32 33.71,45.22 33.71,30.8 37.3,27.2 37.3,24.78 37.18,24.65 v1(36.3,24.65)
  BOTTOM w0.114: U14.7 v1(36.3,24.65)
USB_TO_UART_DP: length 35.5
  TOP w0.114: v1(39.31,49.91) 39.19,50.02 38.6,50.02 37.25,51.37 37.25,52.67 37.14,52.78 U15.7
  LYR3 w0.127: v1(39.31,49.91) 39.21,50.01 38.93,50.01 35.38,46.46 35.38,46.28 35.13,46.03 34.95,46.03 34.7,45.78 34.7,45.6 34.44,45.35 34.26,45.35 34.01,45.1 34.01,30.92 34.26,30.67 34.44,30.67 34.7,30.42 34.7,30.24 34.95,29.99 35.13,29.99 35.38,29.74 35.38,29.56 37.61,27.33 37.61,24.78 37.73,24.65 v1(38.61,24.65)
  BOTTOM w0.114: U14.1 v1(38.61,24.65)
USBA_GND:
  vias: v1(114.35,64.58) v1(114.81,64.6) v1(115.27,64.63)
USBC_DM: length 9.3
  TOP w0.114: J11.A7 63.85,8.71 61.83,8.71 D23.2 60.93,8.72 60.05,8.72 59.92,8.85 59.92,8.92 59.84,9 59.67,9 59.59,8.92 59.59,8.8 59.51,8.72 59.25,8.72 59.13,8.84 59.13,9.28 59.33,9.48 R530.1
  LYR3 w0.076: J11.A7 65.11,9.03 65.35,8.78 65.35,8.12 J11.B7
USBC_DP: length 7.7
  TOP w0.114: J11.B6 64.46,8.13 J11.A6 63.85,8.44 61.81,8.44 D22.2 61.18,8 60.74,8.44 59.13,8.44 58.85,8.72 58.85,9.39 R531.1
USIM_1V8: length 27.7
  LYR3 w0.381: v1(71.27,70.34) 72.82,70.34 73.15,70.01 73.15,66.15 75.01,64.3 75.01,59.93 74.04,58.97 74.04,55.82 v1(74.07,55.79)
  BOTTOM w0.381: v1(74.07,55.79) 75.19,55.79 75.62,55.36 R114.1 ; v1(71.27,70.34) 71.83,70.9 71.83,71.94 71.45,72.33 70.51,72.33 70.21,72.63 TP29.1 70.39,73.4 C116.2 R112.1 71.69,74.14 U21.2
USIM_CLK: length 40.7
  LYR3 w0.121: v1(99.35,33.25) 98.9,32.8 97.44,32.8 95.19,35.05 95.19,42.42 91.03,46.58 91.03,56.48 92.79,58.24 92.79,61.2 93.35,61.76 v1(93.73,61.76)
  BOTTOM w0.121: v1(93.73,61.76) 93.73,62.27 93.36,62.64 C123.1 93.06,62.85 D31.2 92.19,62.97 J16.C3 ; J15.12 v1(99.35,33.25)
USIM_DATA: length 47.7
  LYR3 w0.121: v1(100.15,33.25) 99.32,32.42 97.38,32.42 94.89,34.92 94.89,42.29 90.55,46.62 90.55,56.86 92.22,58.52 92.22,61.85 93.12,62.75 93.12,65.62 v1(93.45,65.95)
  BOTTOM w0.121: J15.10 v1(100.15,33.25) ; v1(93.45,65.95) 94.03,65.37 R115.2 C122.1 93.06,64.88 D30.2 91.67,64.24 J16.C7
USIM_GND: length 7.6
  BOTTOM w0.305: R108.1 107.79,35.83 107.79,35.84
  BOTTOM w0.508: J15.4 102.55,36.64 102.92,37.02 106.61,37.02 107.79,35.84
USIM_RST: length 37.3
  LYR3 w0.121: v1(93.27,61.1) 93.27,57.9 91.42,56.04 91.42,46.67 95.53,42.56 95.53,35.19 97.47,33.25 v1(98.55,33.25)
  BOTTOM w0.121: J15.14 v1(98.55,33.25) ; J16.C2 91.92,60.43 D32.2 92.52,60.61 C128.1 v1(93.27,61.1)
USIM_VDD: length 40.5
  LYR3 w0.508: v1(100.95,36.74) 97.34,36.74 96.01,38.06 96.01,42.76 92.18,46.6 92.18,55.54 94.03,57.39 v1(94.03,59.12) 94.03,61.18 95,62.14 95,63.74 v1(94.58,64.16)
  BOTTOM w0.121: R115.1 v1(94.58,64.16)
  BOTTOM w0.381: J16.C1 91.41,57.89 D33.2 92.52,58.57 C120.1 C121.1 v1(94.03,59.12)
  BOTTOM w0.508: J15.8 v1(100.95,36.74)
USR_LED_B: length 84.9
  TOP w0.121: v1(31.98,69.76) 31.96,69.76 31.86,69.86 U12.8 ; v1(12.83,6.01) 13.52,6.01 14.1,5.42 14.1,4.96 14.65,4.41 J25.5
  LYR3 w0.121: v1(23.68,56.02) 23.68,51.27 12.49,40.09 12.49,39.2 12.04,38.75 9.14,38.75 7.95,37.56 7.95,27.74 6.61,26.4 6.61,23.14 8.24,21.5 8.24,15 12.83,10.41 v1(12.83,6.01) ; v1(31.98,69.76) 31.63,69.76 31.4,69.53 31.4,66.81 29.21,64.63 29.21,62.39 27.66,60.84 v1(27.66,56.02)
  LYR6 w0.121: v1(27.66,56.02) v1(23.68,56.02)
USR_LED_G: length 85.8
  TOP w0.121: v1(31.8,63.74) 31.8,67.96 31.38,68.38 U12.7 ; J25.4 v1(13.65,4.79)
  LYR3 w0.121: v1(25.2,63.33) 25.25,63.28 25.25,51.41 19.05,45.21 19.05,44.49 14.69,40.13 13.96,40.13 13.51,39.67 13.51,38.75 12.51,37.74 10.23,37.74 9.7,37.22 9.7,28.99 12.72,25.97 12.72,23.76 11.12,22.16 11.12,13.17 15.08,9.21 15.08,4.58 14.89,4.38 14.06,4.38 v1(13.65,4.79)
  BOTTOM w0.121: v1(31.8,63.74) 31.57,63.97 25.83,63.97 v1(25.2,63.33)
USR_LED_R: length 83.3
  TOP w0.121: J25.3 12.65,4.61 v1(13.25,5.21) ; v1(31.27,65.95) 31.27,67.78 30.68,68.37 U12.6
  LYR3 w0.121: v1(13.25,5.21) 13.25,10.34 8.49,15.11 8.49,21.61 6.85,23.24 6.85,26.3 8.2,27.64 8.2,37.46 9.24,38.5 12.14,38.5 12.74,39.1 12.74,39.99 24.12,51.37 24.12,63.88 v1(23.88,64.12)
  LYR6 w0.121: v1(31.27,65.95) 26.19,65.95 24.92,64.68 24.13,64.68 23.88,64.43 v1(23.88,64.12)
VETH_DVDDH: length 39.5
  TOP w0.305: v1(46.15,23.56) 46.13,23.53 R82.1
  LYR3 w0.381: v1(34.98,16.95) 42.4,16.95 v1(42.42,16.93)
  BOTTOM w0.305: J18.12 23.57,8.75 24.72,9.89 33.33,9.89 J18.10 36.12,10.4 36.12,14.21 34.52,15.81 C160.1 v1(34.98,16.95) 35.21,16.95 35.56,17.31 FB9.2
  BOTTOM w0.381: v1(42.42,16.93) 43.59,18.1 43.59,22.19 44.22,22.82 45.42,22.82 v1(46.15,23.56)
N17790840: length 2.6
  TOP w0.121: J4.89 56.2,75.33 v1(56.54,74.99)
  BOTTOM w0.121: v1(56.54,74.99) 56.54,75.56 TP14.1
N17790854: length 2.1
  TOP w0.121: J4.91 v1(55.8,75.12)
  BOTTOM w0.121: TP15.1 55.8,75.81 v1(55.8,75.12)
N18106868: length 2
  TOP w0.121: v1(70.46,75.1) 70.2,75.36 J4.19
  BOTTOM w0.121: TP12.1 70.2,75.53 70.2,75.36 v1(70.46,75.1)
N21080778:
  vias: v1(105.06,38.72) v1(105.69,39.64) v1(106.63,38.8) v1(107.67,39.59) v1(108.69,38.67) v1(109.37,39.59) v1(113.29,46.14) v1(113.29,45.3) v1(114.25,46.16) v1(114.25,45.33) v1(114.96,39.43) v1(115.12,45.63) v1(115.17,44.31) v1(115.27,42.28) v1(115.78,41.01) v1(116,43.22)
N21083178: length 4.8
  TOP w0.508: D29.1 10.51,78.82 v1(10.59,78.9)
  BOTTOM w0.508: J12.2 10.9,79.21 v1(10.59,78.9) 10.52,78.83 TP23.1
N21084468: length 2.6
  BOTTOM w0.121: U18.2 14.26,73.39 R105.2 12.72,73.75 C109.2
N21116206:
  vias: v1(103.3,29.96) v1(103.3,29.48) v1(103.3,28.99) v1(103.3,28.51) v1(103.79,29.96) v1(103.79,29.48) v1(103.79,28.99) v1(103.79,28.51) v1(108.13,25.11) v1(108.13,24.62) v1(108.13,24.14) v1(108.13,23.66) v1(108.61,25.11) v1(108.61,24.62) v1(108.61,24.14) v1(108.61,23.66)
N21149713: length 2.6
  BOTTOM w0.121: J14.14 66.44,36.82 65.93,37.34 TP25.1
N21149734: length 3.4
  BOTTOM w0.121: TP26.1 64.34,36.53 65.18,36.53 65.64,36.06 J14.16
N21149896: length 5.4
  BOTTOM w0.121: J14.31 56.44,25.89 56.59,25.74 56.59,23.48 TP27.1
N21149903: length 2.7
  BOTTOM w0.121: TP28.1 55.64,24.78 J14.33
N21150017: length 3.3
  BOTTOM w0.121: J14.45 50.84,26.03 50.08,25.27 R111.2
N21187983: length 4.5
  TOP w0.381: R5.1 109.25,35.28 R2.2 109.34,35.22 v1(109.34,35.91)
  BOTTOM w0.305: D8.2 109.34,34.57 v1(109.34,35.91)
N21187993: length 1.2
  TOP w0.381: Q2.1 107.19,34.77 R5.2
N21188161: length 2
  TOP w0.381: Q2.3 103.57,34.52 D9.1
N21188625: length 29.7
  TOP w0.381: v1(104.02,36.11) 104.02,36.37 D9.2 102.93,36.4 R7.1 R3.2
  LYR3 w0.305: v1(104.02,36.11) 99.9,31.99 97.21,31.99 93.88,35.32 93.88,42.28 91.48,44.68 v1(90.16,44.68)
  BOTTOM w0.305: C1.2 v1(90.16,44.68) 90.11,44.63 Q1.4
N21206327: length 6.5
  TOP w0.121: X3.2 5.74,69.28 C103.1 6.7,70.27 7.36,70.93 R101.2 7.43,70.99 8.03,71.59 9.27,71.59 9.98,72.3 U16.1
N21206924: length 5.2
  TOP w0.121: X3.1 8.79,69.21 7.98,70.02 C102.2 7.94,70.28 R101.1 8.24,71.23 9.38,71.23 9.58,71.03 U16.2
N21339151: length 1.8
  TOP w0.121: R110.1 v1(59.95,33.99)
  BOTTOM w0.121: v1(59.95,33.99) 60.04,34.08 J14.22
N21339355: length 4.4
  BOTTOM w0.121: J15.22 92.15,36.59 R109.1
N21664516: length 1
  TOP w0.121: R37.1 59.88,28.02 U3.8
N21767500: length 28.8
  TOP w0.121: R24.2 38.3,66.56 48.01,66.56 48.87,67.42 54.89,67.42 58.52,71.06 62.38,71.06 63,71.67 J4.56
N21767503: length 27.9
  TOP w0.121: R25.2 37.9,66.97 47.83,66.97 48.64,67.77 54.76,67.77 58.37,71.39 62.03,71.39 62.6,71.96 J4.58
N21891930: length 3.8
  TOP w0.121: R49.1 53.02,26.27 53.32,25.97 53.87,25.97 54.2,26.29 R47.1 54.31,26.2 54.31,25.72 C56.1 54.18,24.52 X1.1
N21894342: length 6.4
  TOP w0.121: X1.3 52.26,22.38 53.34,23.46 53.34,24.8 53.01,25.14 C57.1 53.01,25.8 52.51,26.3 R49.2 52.34,26.5 U4.60
N22026897: length 27.4
  LYR3 w0.102: J18.1 25.58,12.63 25.58,12.33 25.76,12.11 26.08,12.06 26.67,12.48 26.67,13.55 22.79,17.44 22.79,21.37 23.4,21.98 23.4,23.76 23.02,24.14 20.73,24.14 19.99,24.88 15.22,24.88 14.79,25.31 14.79,26 13.92,26.86 v1(13.92,27.02)
  BOTTOM w0.095: T1.24 v1(13.92,27.02)
N22026906: length 27.4
  LYR3 w0.102: v1(15.92,26.99) 15.92,26.83 15.09,26 15.09,25.44 15.34,25.18 20.12,25.18 20.86,24.45 23.14,24.45 23.7,23.89 23.7,21.86 23.09,21.25 23.09,17.56 26.98,13.68 26.98,12.34 26.91,12.27 26.54,12.01 26.5,11.78 26.99,11.1 J18.2
  BOTTOM w0.095: T1.22 v1(15.92,26.99)
N22026915: length 26.2
  BOTTOM w0.095: T1.21 16.92,26.88 17.76,26.05 17.76,25.42 18.62,24.56 18.62,20.62 22.98,16.27 27.29,16.27 29.62,13.94 29.62,12.48 29.24,12.01 28.53,11.84 28.25,11.84 27.99,12.1 27.99,12.53 28.23,12.77 J18.3
N22026957: length 22.6
  BOTTOM w0.095: T1.15 22.92,26.95 23.78,26.1 23.78,25.75 32.06,17.47 32.06,15.19 33.24,14.01 33.96,14.01 34.42,13.55 34.42,12.58 34.08,12.24 33.88,12.09 33.38,12.17 33.25,12.35 33.25,12.68 J18.7
N22026966: length 22.7
  BOTTOM w0.095: T1.13 24.92,26.99 24.06,26.12 24.06,25.87 32.34,17.59 32.34,15.3 33.35,14.29 34.08,14.29 34.7,13.67 34.7,12.46 34.26,12.02 34.13,11.93 34.11,11.8 34.61,11.1 J18.8
N22027038: length 1.4
  BOTTOM w0.584: T1.14 v1(23.92,27.1) v1(23.92,26.66)
  vias: v1(21.67,19.65) v1(21.67,19.16) v1(21.97,23.68) v1(22.43,23.68)
N22027110: length 1.4
  BOTTOM w0.584: T1.20 v1(17.92,27.1) v1(17.92,26.66)
  vias: v1(8.97,19.62) v1(9.53,19.65) v1(17.07,23.46) v1(17.63,23.46)
N22027117: length 1.4
  BOTTOM w0.584: v1(20.92,26.66) v1(20.92,27.1) T1.17
  vias: v1(17.96,19.65) v1(17.99,19.09) v1(20.4,23.41) v1(20.93,23.41)
N22027433: length 19.9
  BOTTOM w0.121: R155.2 36.83,17 36.83,14.74 36.48,14.39 36.48,10.2 35.77,9.49 35.77,8.24 35.13,7.61 27,7.61 J18.11
N22027462: length 8.8
  BOTTOM w0.121: R160.2 37.16,16.34 37.16,14.64 36.76,14.24 J18.9
N22028382: length 1.4
  BOTTOM w0.584: T1.23 v1(14.92,27.1) v1(14.92,26.66)
  vias: v1(11.76,19.62) v1(12.19,19.62) v1(13.95,23.46) v1(14.43,23.46)
N22029929:
  vias: v1(27.89,19.93) v1(27.89,19.49) v1(28.32,19.93) v1(28.32,19.49)
N22030276: length 1.9
  TOP w1.27: D51.4 9.42,17 R151.1
N22030277: length 1.9
  TOP w1.27: D51.3 11.82,16.97 R152.1
N22038029: length 1.4
  TOP w0.889: R156.2 C154.1
N22038032:
  vias: v1(13.11,20.59) v1(13.57,20.56) v1(14.05,20.56) v1(14.48,20.56) v1(16.79,21.45) v1(16.79,21.02) v1(20.09,21.47) v1(20.09,21.04)
N22038068: length 1.4
  TOP w0.889: C155.1 R157.2
N22038120: length 1.4
  TOP w0.889: C156.1 R158.2
N22038172: length 1.5
  BOTTOM w0.889: R159.2 23.32,22.69 C157.1
N22078660: length 26.2
  BOTTOM w0.095: J18.6 32.07,11.1 30.38,11.89 29.9,12.27 29.9,14.06 27.41,16.55 23.09,16.55 18.9,20.74 18.9,24.68 18.04,25.54 18.04,26.05 18.92,26.93 T1.19
N22078676: length 24
  LYR3 w0.102: v1(21.92,26.99) 21.92,26.81 21.14,26.02 21.14,25.79 21.24,25.69 23.4,25.69 25,24.09 25,21.5 24.36,20.87 24.36,17.72 26.52,15.56 27.84,15.56 29.7,13.7 29.7,12.62 30.05,12.26 30.17,12.17 30.36,12.03 30.75,12.1 30.94,12.32 30.94,12.63 J18.5
  BOTTOM w0.095: T1.16 v1(21.92,26.99)
N22078685: length 24
  LYR3 w0.102: v1(19.92,27.02) 19.92,26.91 20.83,26 20.83,25.67 21.11,25.39 23.27,25.39 24.69,23.96 24.69,21.63 24.06,20.99 24.06,17.59 26.39,15.25 27.71,15.25 29.39,13.58 29.39,12.49 29.86,12.02 29.99,11.93 29.99,11.92 30.02,11.78 29.53,11.1 J18.4
  BOTTOM w0.095: T1.18 v1(19.92,27.02)
N22567639: length 3.3
  TOP w0.508: v1(25.18,39.44) 25.18,39.44 v1(23.92,38.19)
  BOTTOM w0.508: C153.1 v1(25.18,39.44) ; T1.11 v1(23.92,38.19)
N22567644: length 2.8
  TOP w0.508: v1(20.9,38.21) 20.74,38.36 v1(20.74,39.49)
  BOTTOM w0.508: v1(20.9,38.21) 20.92,38.19 T1.8 ; C152.1 v1(20.74,39.49)
N22567654: length 3.1
  TOP w0.508: v1(17.92,38.19) 19.04,39.31 v1(19.04,39.42)
  BOTTOM w0.508: T1.5 v1(17.92,38.19) ; C151.1 v1(19.04,39.42)
N22567659: length 3.2
  TOP w0.508: v1(13.93,39.42) 13.93,39.23 14.84,38.32 v1(14.84,38.24)
  BOTTOM w0.508: v1(14.84,38.24) 14.84,38.21 14.92,38.13 T1.2 ; C150.1 v1(13.93,39.42)
N22695835: length 2.8
  BOTTOM w0.121: J14.8 68.84,36.87 68.36,37.36 TP24.1
N22714565: length 2.8
  BOTTOM w0.121: R103.1 60.12,78.6 60.63,79.11 R102.2 60.63,79.26 61.48,80.11 U17.7
N23370571: length 1.8
  TOP w0.121: U4.11 56.42,33.48 R41.2
N23400557: length 2.1
  TOP w0.121: U4.63 53.84,27.24 53.99,27.09 54.17,27.09 R42.2
N23401903: length 1.3
  TOP w0.254: R43.2 44.93,31.98 U4.41
N23402124: length 1.8
  TOP w0.121: U4.50 47.34,26.33 R45.2
N23405519: length 1.8
  TOP w0.121: R47.2 53.65,26.32 52.84,27.12 U4.61
N23449459: length 3.9
  TOP w0.121: J11.A5 64.71,7.23 64.79,7.14 66.47,7.14 R94.1
N23449477: length 2.8
  TOP w0.121: J11.B5 65.1,9.29 R95.1
N23449775: length 3.6
  BOTTOM w0.203: U14.9 37.46,26.17 C98.1
  BOTTOM w0.305: C98.1 37.52,27.01 D25.2
  BOTTOM w0.381: D25.2 D24.2
N23449933: length 4.7
  TOP w0.121: U15.5 36.14,52.73 D26.1 34.15,51.68 R99.1 R98.2
N23450082: length 1.4
  TOP w0.121: U15.4 34.53,53.69 R100.1
N23450096: length 1.1
  BOTTOM w0.121: U14.8 37.06,25.85 R97.1
N23451512: length 1.6
  TOP w0.121: R53.2 96.4,65.73 U5.28
N23451530: length 11.1
  TOP w0.121: U5.22 v1(93.75,69.95)
  BOTTOM w0.121: v1(93.75,69.95) 88.76,69.95 85.89,72.82 R54.2
N23451550: length 12.2
  TOP w0.121: U5.24 v1(94.87,68.95)
  BOTTOM w0.121: v1(94.87,68.95) 94.32,69.51 88.52,69.51 85.23,72.8 R55.2
N23451563: length 12.9
  TOP w0.121: U5.25 v1(94.64,68.45)
  BOTTOM w0.121: v1(94.64,68.45) 94.64,68.49 93.96,69.18 88.48,69.18 R56.2
N23451623: length 1.4
  TOP w0.121: R57.1 99.9,73.16 U5.11
N23451671: length 2
  TOP w0.121: U5.35 99.9,66.03 100,65.92 v1(100,65.87)
  BOTTOM w0.121: v1(100,65.87) 100.1,65.98 100.1,66.99 R58.1
N23451839: length 3
  TOP w0.305: U5.34 v1(99.4,65.91)
  BOTTOM w0.305: v1(99.4,65.91) 99.32,65.99 C70.2 98.66,67.25 C69.2
N23451845: length 2.6
  TOP w0.121: R62.1 95.05,73.35 95.05,71.67 95.27,71.45 U5.19
N23451875: length 2.8
  TOP w0.305: U5.14 v1(98.4,72.96)
  BOTTOM w0.305: C71.2 98.02,71.89 C72.2 98.66,72.7 v1(98.4,72.96)
N23451879: length 10.4
  TOP w0.121: U5.21 v1(94.34,70.45)
  BOTTOM w0.121: R63.1 86.58,72.59 88.72,70.45 v1(94.34,70.45)
N23451944: length 1.5
  TOP w0.121: U5.32 98.4,65.41 R69.2
N23451981: length 1.5
  TOP w0.121: R67.1 95.91,73.35 96.4,72.86 U5.18
N23452007: length 5.5
  TOP w0.121: X2.3 101.2,63.98 C75.1 100.78,65.47 99.13,65.47 R70.2 98.85,66.55 U5.33
N23452009: length 3.4
  TOP w0.121: U5.20 94.95,70.95 94.59,71.31 R68.1
N23452027: length 6.8
  TOP w0.121: R69.1 R70.1 98.85,64.46 99.26,64.05 C74.1 99.73,63.05 100.21,62.57 101.73,62.57 102.76,61.55 X2.1
N23452966: length 7.6
  BOTTOM w0.114: L5.1 114.08,61.96 112.85,61.96 112.42,61.53 D18.2 112.38,61.52 111.93,61.97 110.63,61.97 109.55,60.9 108.33,60.9 108.22,60.78 J8.B2
N23452985: length 7.6
  BOTTOM w0.114: J8.B3 108.22,61.29 108.33,61.17 109.44,61.17 110.51,62.25 111.95,62.25 112.4,62.7 D19.2 112.42,62.68 112.85,62.24 114.08,62.24 L5.4
N23455465: length 7.3
  BOTTOM w0.121: R36.1 9.74,17.02 9.07,17.7 D12.2 5.38,17.7 SW1.2
N23456906: length 1.4
  BOTTOM w0.121: R64.2 77.95,73.73 U6.3
N23459666: length 3
  TOP w0.121: v1(46.87,37.52) 46.97,37.41 48.62,37.41 48.84,37.19 U4.28
  BOTTOM w0.121: 46.86,37.53 v1(46.87,37.52) 46.75,37.4 R50.1
N23461225: length 1.3
  TOP w0.121: R48.1 44.88,30.48 U4.44
N23461314: length 2.7
  TOP w0.121: U4.45 45.58,29.98 v1(45.57,29.98)
  BOTTOM w0.121: v1(45.57,29.98) 45.23,30.32 44.67,30.32 44.63,30.28 TP19.1
N23463209: length 20.6
  TOP w0.121: R83.2 44.48,21.74 44.48,18.35 43.33,17.2 43.33,14.45 43.81,13.97 44.45,13.33 46.63,13.33 47.37,12.58 47.37,7.28 45.89,5.79 J10.10
N23463212: length 23.9
  TOP w0.121: J10.11 47.63,10.06 47.63,12.81 46.87,13.58 44.55,13.58 43.58,14.55 43.58,16.99 44.81,18.22 44.81,21.8 R84.2
N23463479: length 13.6
  TOP w0.121: U4.20 52.84,37.47 51.22,39.1 45.85,39.1 44.34,37.59 43.33,37.59 v1(42.47,36.73)
  BOTTOM w0.121: v1(42.47,36.73) TP18.1
N23466024: length 2.4
  TOP w0.121: U12.18 28.18,72.78 27.97,72.99 26.75,72.99 R85.2
N23466170: length 1.3
  TOP w0.121: U12.23 27.07,69.86 26.54,69.32 R92.1
N23466179: length 1.5
  TOP w0.121: R93.1 27.18,69.36 U12.24
N23473877: length 5.5
  TOP w0.508: B1.1 v1(20.32,79.92)
  BOTTOM w0.508: R38.2 18.02,78.4 D13.2 19.13,78.55 20.32,79.74 v1(20.32,79.92)
N23473909: length 5.4
  TOP w0.508: B1.2 20.32,74.38 v1(19.5,75.21)
  BOTTOM w0.508: Q3.3 19.96,74.75 v1(19.5,75.21) 19.13,75.58 D13.1
N23473945: length 2.5
  BOTTOM w0.121: Q3.1 23.18,73.65 R40.1 R39.2
N23500588: length 6.9
  BOTTOM w0.121: J62.68 22.04,53.19 22.35,52.87 22.35,49.34 21.23,48.22 OSC1.3
N23502047: length 15.8
  LYR3 w0.121: v1(26.24,57.39) 25.61,56.76 25.61,50.23 v1(25.33,49.95)
  BOTTOM w0.121: R175.2 25.69,49.58 v1(25.33,49.95) ; J62.54 22.21,56.69 22.91,57.39 v1(26.24,57.39)
N23529653: length 23.3
  TOP w0.121: J4.80 58.2,71.65 54.59,68.03 48.39,68.03 47.87,67.51 R27.2
N23529656: length 22.5
  TOP w0.121: R28.2 54.27,68.3 57.8,71.83 J4.82
N23611485: length 2.6
  BOTTOM w0.121: U1.4 77.3,37.39 R12.1
N23611490: length 1.9
  BOTTOM w0.305: U1.6 69.76,38.66 68.8,39.62 C15.1
N23612078: length 13.3
  LYR6 w0.381: v1(67.95,46.46) 69.78,44.64 69.78,42.72 71.3,41.2 v1(76.18,41.2)
  BOTTOM w0.381: C5.1 v1(67.95,46.46) ; U1.1 v1(76.18,41.2)
N23612081: length 1.5
  BOTTOM w0.381: R9.1 65.66,44.98 C5.2
N23613464: length 3.1
  BOTTOM w0.381: R9.2 67.17,42.72 D10.2
N23613978: length 4.8
  BOTTOM w0.121: R8.2 78.66,38.21 77.9,38.21 77.59,37.9 R10.2 76.75,38.66 U1.3
N23614867: length 6.2
  BOTTOM w0.305: U1.5 69.17,37.39 68.18,38.37 R14.1 66.65,39.35 R13.2 64.9,39.35 C17.2
N23615765: length 1.2
  BOTTOM w0.508: R11.2 65.64,47.95 C16.1
N23616333: length 7.5
  LYR6 w0.381: v1(48.52,42.62) 52.85,42.62 v1(53.75,41.72)
  BOTTOM w0.381: v1(53.75,41.72) 54.26,41.21 U2.1 ; C18.1 v1(48.52,42.62)
N23616335: length 1.5
  BOTTOM w0.381: R15.1 46.35,42.6 C18.2
N23616337: length 1.9
  BOTTOM w0.381: U2.8 47.91,41.21 R15.2
N23616378: length 4.6
  BOTTOM w0.121: R181.2 57.61,38.33 R16.2 57.31,38.95 56.64,38.95 56.4,38.71 R17.2 56.33,38.67 U2.3
N23616505: length 1.7
  BOTTOM w0.121: U2.4 56.39,37.4 R19.1
N23616509: length 3.8
  BOTTOM w0.305: C30.2 48.08,38.65 48.36,38.37 R20.2 48.35,38.02 R21.1 48.87,37.06 49.22,37.4 U2.5
N23616593: length 2.8
  BOTTOM w0.305: U2.6 48.9,38.67 48.61,38.96 48.61,39.57 48.08,40.1 C28.1
N23616615: length 1.3
  BOTTOM w0.508: C29.1 43.72,48.49 R18.2
N23711005: length 11.5
  BOTTOM w0.114: L4.3 114.02,59.75 112.88,59.75 112.42,59.29 D15.2 112.37,59.27 111.9,59.74 110.12,59.74 109.24,58.86 107.58,58.86 106.83,59.61 106.83,60.48 106.41,60.9 105.71,60.9 105.6,60.78 J8.A2
N23711301: length 11.5
  BOTTOM w0.114: J8.A3 105.6,61.29 105.71,61.17 106.53,61.17 107.11,60.59 107.11,59.73 107.7,59.14 109.12,59.14 110,60.02 111.88,60.02 112.35,60.5 D14.2 112.42,60.49 112.88,60.03 114.07,60.03 L4.2
N23781625: length 1.4
  BOTTOM w0.121: R651.2 28.72,34.11 U33.6
N23800931: length 0.9
  BOTTOM w0.305: R652.2 65.68,38.49 R13.1
N23801005: length 1.9
  BOTTOM w0.305: R20.1 47.43,38.33 47.09,38.67 46.49,38.67 R653.2
N23918848: length 8.5
  BOTTOM w0.762: J24.22 5.24,52.04 4.7,51.5 4.7,50.07 6.96,47.81 FB26.1
N23953873: length 27.4
  TOP w0.121: R6.2 64.13,78.41 63.91,78.62 v1(63.91,79.77) ; J4.28 v1(68.6,72.07)
  LYR3 w0.121: v1(68.6,72.07) 68.79,71.88 68.79,66.9 v1(68.6,66.71) ; v1(63.76,66.73) 63.06,66.73 62.59,67.19 62.59,76.95 63.91,78.27 v1(63.91,79.77)
  BOTTOM w0.121: v1(63.76,66.73) 68.59,66.73 v1(68.6,66.71)
N23953904: length 4.6
  TOP w0.121: J4.31 67.8,77.58 66.97,78.41 R1.1
N23982561: length 16.8
  TOP w1.016: C133.1 72.95,16.65 63.24,16.65 U22.2
N23982687: length 2.3
  TOP w0.121: U23.4 80.54,22.73 80.34,22.92 R119.1 R122.2
N23982695: length 1.8
  TOP w0.121: U23.3 80.54,18.74 80.77,18.5 R120.1
N23982720: length 4.1
  BOTTOM w0.381: R118.2 76,16.88 TP33.1 78.75,17.77 D34.2
N24049462: length 2.8
  TOP w0.121: R129.2 16.91,59.29 D41.2 15.83,58.97 J26.5
N24050469: length 4.9
  TOP w0.121: R87.2 R86.2 16.36,65.39 D44.2 15.57,65.18 15.34,64.96 15.34,63.87 14.85,63.37 J26.9

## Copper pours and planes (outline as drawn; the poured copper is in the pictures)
3V3_RS485 on TOP: 62.21,25.06 61.95,25.31 61.95,27.32 62.23,27.6 63.1,27.6 63.27,27.42 63.27,26.99 63.1,26.81 63.1,26.2 63.22,26.07 65.94,26.07 66.07,25.95 66.07,25.28 65.84,25.06
5V_ISO_INPUT on TOP: 78.89,19.72 78.89,18.25 78.69,18.05 78.69,17.11 78.56,16.98 77.75,16.98 77.47,17.26 77.47,18.3 76.94,18.83 76.53,18.83 76.1,19.27 76.1,21.42 76.35,21.68 77.22,21.68 77.65,21.25 77.65,19.72 77.9,19.47 78.56,19.47 78.82,19.72
5V_TYPC on TOP: 65.08,10.65 64.06,10.65 63.43,10.02 62.66,10.02 62.18,10.5 62.18,11.72 61.52,12.38 61.52,12.99 61.42,13.09 60.68,13.09 60.51,12.92 60.51,12.41 61.11,11.8 61.11,9.99 61.39,9.71 61.65,9.71 62.13,9.23 63.65,9.23 64.47,10.04 65.08,10.04 65.2,10.17 65.2,10.53
5V_TYPC on TOP: 60.71,2.2 60.71,2.6 61.17,3.06 61.17,3.92 60.94,4.15 60.15,4.15 59.84,3.85 59.84,3.11 59.57,2.83 59.18,2.83 59.03,2.68 59.03,2.12 59.18,1.97 60.48,1.97
5V_TYPC on BOTTOM: 10.92,34.81 9.73,34.81 9.63,34.91 9.63,35.29 9.73,35.39 10.04,35.39 10.62,35.98 11.25,35.98 11.41,35.83 11.41,35.29
5V_TYPC on LYR3: 39.3,54.11 39.3,52.82 35.59,49.11 31.96,49.11 28.91,46.06 28.91,39.97 31.04,37.83 31.04,31.61 35.11,27.55 35.11,21.27 34.62,20.79 33.71,20.79 33.17,21.32 33.17,26.38 28.81,30.75 28.81,36.41 26.32,38.9 26.32,46.62 30.36,50.66 33.35,50.66 34.14,51.45 34.14,55.18 34.44,55.49 37.92,55.49
5V_TYPC on LYR3: 65.05,6.03 63.76,6.03 63.43,6.36 62.36,6.36 62.11,6.11 62.11,2.86 61.7,2.45 59.92,2.45 59.59,2.78 59.59,6.16 60.48,7.05 60.48,12.79 60.66,12.97 61.42,12.97 61.67,12.71 61.67,10.98 62.74,9.92 63.32,9.92 64.06,10.65 65,10.65 65.2,10.45 65.2,6.18
5V_TYPC on LYR6: 33.99,23.41 42.85,23.41 43.74,22.52 48.41,22.52 49.94,20.99 60.73,20.99 61.72,20 61.72,12.08 61.52,11.87 59.9,11.87 59.31,12.46 59.31,17.66 57.89,19.09 44.73,19.09 42.22,21.6 33.89,21.6 33.66,21.83 33.66,23.08 ; 1 cut-out
5V_TYPC on LYR6: 9.12,35.72 9.12,37.35 9.88,38.11 28.78,38.11 29.01,37.88 29.01,36.92 28.76,36.66 11.56,36.66 11.38,36.49 11.38,35.7 11.2,35.52 9.32,35.52
+1.8V_OUT on BOTTOM: 56.72,71.77 56.72,72.88 56.49,73.11 56.14,73.11 55.96,72.94 55.96,71.77 56.11,71.61 56.57,71.61
GND on TOP: 32.41,49.49 34.27,49.49 34.6,49.16 34.6,46.6 33.99,45.99 32.31,45.99 32.08,46.21 32.08,49.16
GND on TOP: 104.83,51.4 104.29,51.4 103.81,50.91 102.29,50.91 101.83,51.37 101.45,51.37 100.61,50.53 98.91,50.53 98.58,50.2 98.58,47.56 98.78,47.36 99.65,47.36 99.88,47.59 99.88,48.35 100.36,48.83 103.1,48.83 103.91,49.64 103.91,50.3 104.35,50.74 104.83,50.74 105.01,50.91 105.01,51.22
GND on TOP: outline of 156 points within 1.88,1.1 117.43,83.4 ; 40 cut-outs
GND on BOTTOM: 16.08,20.48 16.08,20.05 15.78,19.75 15.19,19.75 15.04,19.9 15.04,20.61 15.22,20.79 15.78,20.79
GND on BOTTOM: 36.4,46.72 34.17,46.72 33.35,45.91 32.57,45.91 32.36,46.11 32.36,47.26 33.99,48.88 36.55,48.88 36.68,48.75 36.68,47
GND on BOTTOM: outline of 136 points within 1.88,1.1 117.43,83.4 ; 25 cut-outs
GND on LYR2_GND: outline of 136 points within 1.88,1.1 117.43,83.4
GND on LYR4_GND: outline of 142 points within 1.88,1.1 117.43,83.4
GND on LYR7_GND: outline of 130 points within 1.88,1.1 117.43,83.4
GND_DO on TOP: 94.95,21.75 96.22,21.75 96.34,21.63 96.34,19.19 96.09,18.93 94.52,18.93 94.49,18.96 94.49,21.3
GND_EARTH on TOP: 10.04,20.87 8.77,20.87 8.51,21.12 8.51,22.82 8.79,23.1 10.04,23.1 10.34,22.8 10.34,21.17
GND_EARTH on TOP: outline of 94 points within 0.23,0.22 119.48,83.4
GND_EARTH on BOTTOM: outline of 108 points within 0.23,0.22 119.48,83.4 ; 1 cut-out
GND_EARTH on LYR2_GND, LYR3: outline of 83 points within 0.23,0.22 119.48,83.4
GND_EARTH on LYR4_GND: outline of 113 points within 0.23,0.22 119.48,83.4
GND_EARTH on LYR5_PWR: outline of 103 points within 0.23,0.22 119.48,83.4
GND_EARTH on LYR6: outline of 119 points within 0.23,0.22 119.48,83.4 ; 1 cut-out
GND_EARTH on LYR7_GND: outline of 117 points within 0.23,0.22 119.48,83.4 ; 1 cut-out
GND_ISO on TOP: 59.26,18.96 58.98,18.96 58.12,19.82 58.12,21.88 57.81,22.19 56.24,22.19 55.91,21.86 55.91,19.87 58.14,17.64 59.18,17.64 59.41,17.87 59.41,18.81
